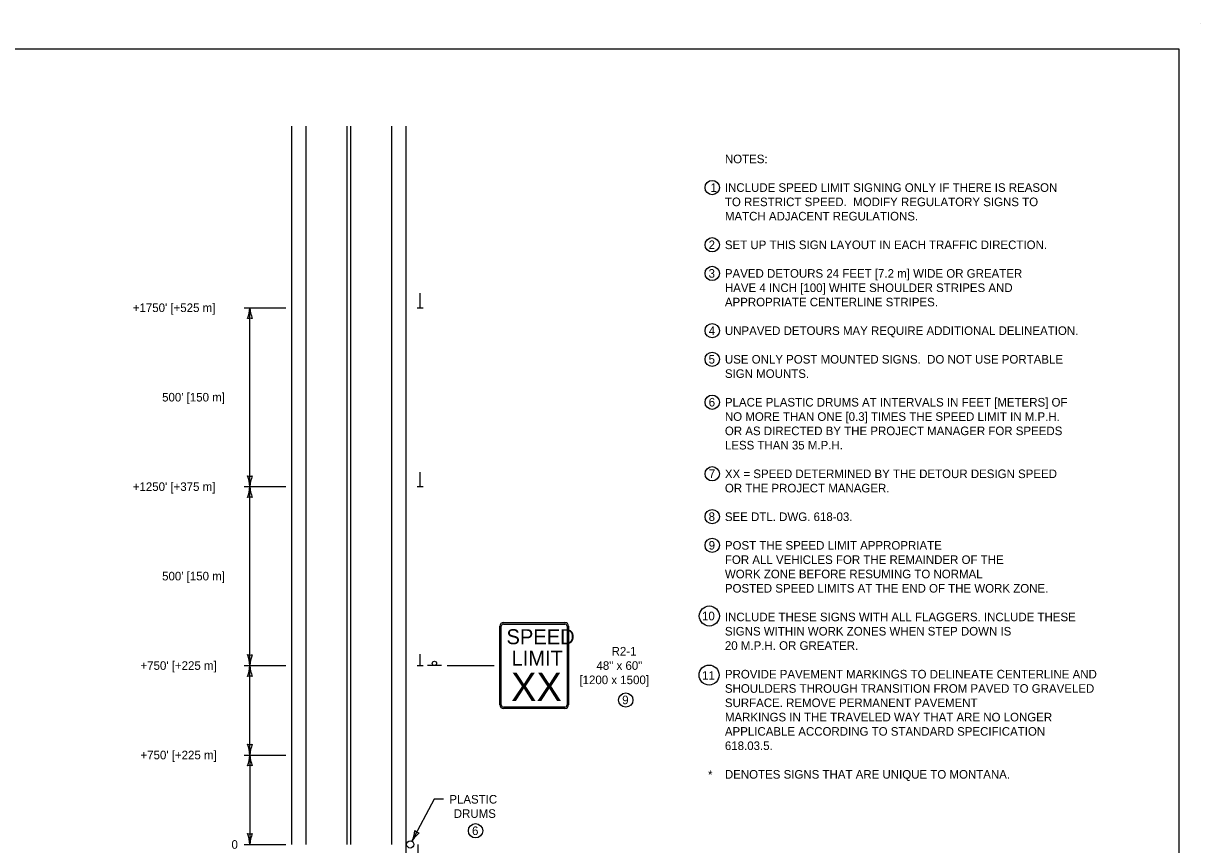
# Model space of a CAD drawing. Extents: x 49991.4 to 50021, y 49987.6 to 50011.4.
# Drawn here: x 50008.68 to 50016.9, y 49993.44 to 49999.18 of the extents above; entities that cross this region are included whole.
import ezdxf

# ---------------------------------------------------------------- set-up
doc = ezdxf.new("R2010")
doc.units = 0
for name, color, linetype in [('Level 1', 7, 'Continuous'), ('Level 2', 7, 'Continuous'), ('Level 3', 7, 'Continuous')]:
    doc.layers.add(name, color=color, linetype=linetype)

msp = doc.modelspace()

# ---------------------------------------------------------------- linework, layer by layer
at = {"layer": 'Level 1'}
for p, q in [((50016.9001, 49999.1756), (50016.9001, 49999.1756)), ((50010.5474, 49998.459), (50010.5474, 49993.4398)), ((50010.6474, 49998.459), (50010.6474, 49993.4398)), ((50010.9349, 49998.459), (50010.9349, 49993.4398)), ((50010.9599, 49998.459), (50010.9599, 49993.4398)), ((50011.2474, 49998.459), (50011.2474, 49993.4398)), ((50011.3474, 49998.459), (50011.3474, 49989.3327)), ((50011.4474, 49997.1898), (50011.4474, 49997.2918)), ((50011.4271, 49997.1898), (50011.4677, 49997.1898)), ((50011.4474, 49995.9398), (50011.4474, 49996.0417)), ((50011.4271, 49995.9398), (50011.4677, 49995.9398)), ((50012.0041, 49994.4148), (50012.0041, 49994.9648)), ((50012.0141, 49994.4148), (50012.0141, 49994.9648)), ((50012.0291, 49994.9898), (50012.4591, 49994.9898)), ((50012.0291, 49994.9798), (50012.4591, 49994.9798)), ((50012.4741, 49994.9648), (50012.4741, 49994.4148)), ((50012.4841, 49994.9648), (50012.4841, 49994.4148)), ((50011.4474, 49994.6898), (50011.4474, 49994.7682)), ((50011.4271, 49994.6898), (50011.4677, 49994.6898)), ((50011.5954, 49994.6898), (50011.4994, 49994.6898)), ((50012.4591, 49994.3998), (50012.0291, 49994.3998)), ((50012.4591, 49994.3898), (50012.0291, 49994.3898)), ((50011.4344, 49993.3584), (50011.4343, 49993.4398))]:
    msp.add_line(p, q, dxfattribs=at)
msp.add_lwpolyline([(49999.3835, 49998.9992), (50016.7501, 49998.9992), (50016.7501, 49987.7988), (49999.3835, 49987.7988)], close=True, dxfattribs=at)
for centre, radius in [((50011.5473, 49994.705), 0.0152), ((50011.3779, 49993.4398), 0.025)]:
    msp.add_circle(centre, radius, dxfattribs=at)
for centre, radius, start, end in [((50012.029, 49994.9648), 0.025, 90, 180), ((50012.029, 49994.9648), 0.015, 90, 180), ((50012.459, 49994.9648), 0.025, 0, 90), ((50012.459, 49994.9648), 0.015, 0, 90), ((50012.029, 49994.4148), 0.025, 180, 270), ((50012.029, 49994.4148), 0.015, 180, 270), ((50012.459, 49994.4148), 0.025, 270, 0), ((50012.459, 49994.4148), 0.015, 270, 0)]:
    msp.add_arc(centre, radius, start, end, dxfattribs=at)
at = {"layer": 'Level 2'}
for centre, radius in [((50013.488, 49998.0295), 0.05), ((50013.488, 49997.6295), 0.05), ((50013.488, 49997.4295), 0.05), ((50013.488, 49997.0295), 0.05), ((50013.488, 49996.8295), 0.05), ((50013.488, 49996.5295), 0.05), ((50013.488, 49996.0295), 0.05), ((50013.488, 49995.7297), 0.05), ((50013.488, 49995.5298), 0.05), ((50013.468, 49995.036), 0.07), ((50013.466, 49994.6235), 0.07), ((50012.8839, 49994.4487), 0.05), ((50011.8342, 49993.5356), 0.05)]:
    msp.add_circle(centre, radius, dxfattribs=at)
at = {"layer": 'Level 3'}
for p, q in [((50010.2174, 49997.1898), (50010.5074, 49997.1898)), ((50010.2574, 49995.9398), (50010.2574, 49997.1898)), ((50010.2174, 49995.9398), (50010.5074, 49995.9398)), ((50010.2574, 49994.6898), (50010.2574, 49995.9398)), ((50010.2174, 49994.6898), (50010.5074, 49994.6898)), ((50010.2574, 49994.0648), (50010.2574, 49994.6898)), ((50011.6354, 49994.6898), (50011.9641, 49994.6898)), ((50010.2174, 49994.0648), (50010.5074, 49994.0648)), ((50010.2574, 49994.0648), (50010.2574, 49993.4398)), ((50011.5443, 49993.7556), (50011.3897, 49993.4618)), ((50011.6106, 49993.7556), (50011.5443, 49993.7556)), ((50010.2174, 49993.4398), (50010.5074, 49993.4398))]:
    msp.add_line(p, q, dxfattribs=at)
for centre, radius, start, end in [((50010.0247, 49997.2013), 0.233, 337.92284, 357.17269), ((50010.4795, 49997.199), 0.2223, 182.36048, 202.54399), ((50010.2574, 49997.0616), 0.0548, 72.13882, 107.86118), ((50010.0353, 49995.9306), 0.2223, 2.36048, 22.54399), ((50010.2574, 49996.068), 0.0548, 252.13882, 287.86118), ((50010.4901, 49995.9283), 0.233, 157.92284, 177.17269), ((50010.0353, 49995.949), 0.2223, 337.45491, 357.63841), ((50010.2574, 49995.8116), 0.0548, 72.13771, 107.86008), ((50010.4901, 49995.9513), 0.233, 182.82621, 202.07606), ((50010.2574, 49994.818), 0.0548, 252.13771, 287.86008), ((50010.0247, 49994.6783), 0.233, 2.82621, 22.07606), ((50010.4795, 49994.6806), 0.2223, 157.45491, 177.63841), ((50010.0247, 49994.7013), 0.233, 337.92284, 357.17269), ((50010.4795, 49994.699), 0.2223, 182.36048, 202.54399), ((50010.2574, 49994.5616), 0.0548, 72.13882, 107.86118), ((50010.0352, 49994.0556), 0.2223, 2.36048, 22.54399), ((50010.2574, 49994.193), 0.0548, 252.13882, 287.86118), ((50010.4901, 49994.0533), 0.233, 157.92284, 177.17269), ((50010.0247, 49994.0763), 0.233, 337.92284, 357.17269), ((50010.4795, 49994.074), 0.2223, 182.36048, 202.54399), ((50010.2574, 49993.9366), 0.0548, 72.13882, 107.86118), ((50010.0352, 49993.4306), 0.2223, 2.36048, 22.54399), ((50010.2574, 49993.568), 0.0548, 252.13882, 287.86118), ((50010.4901, 49993.4283), 0.233, 157.92284, 177.17269), ((50011.1788, 49993.5609), 0.233, 334.82731, 354.07716), ((50011.5815, 49993.3494), 0.2223, 129.45601, 149.63952), ((50011.4499, 49993.575), 0.0548, 224.13882, 259.86118)]:
    msp.add_arc(centre, radius, start, end, dxfattribs=at)

# ---------------------------------------------------------------- texts
at = {"layer": 'Level 1'}
for s, height, p in [('SPEED', 0.10512, (50012.0503, 49994.8388)), ('LIMIT', 0.10512, (50012.0857, 49994.6887)), ('XX', 0.1989, (50012.0825, 49994.4414))]:
    msp.add_text(s, height=height, dxfattribs=at).set_placement(p)
at = {"layer": 'Level 2'}
for s, p in [('NOTES:', (50013.5768, 49998.1996)), ('1', (50013.4768, 49997.9997)), ('INCLUDE SPEED LIMIT SIGNING ONLY IF THERE IS REASON', (50013.5768, 49997.9996)), ('TO RESTRICT SPEED.  MODIFY REGULATORY SIGNS TO', (50013.5768, 49997.8996)), ('MATCH ADJACENT REGULATIONS.', (50013.5768, 49997.7996)), ('2', (50013.4629, 49997.5997)), ('SET UP THIS SIGN LAYOUT IN EACH TRAFFIC DIRECTION.', (50013.5768, 49997.5996)), ('3', (50013.4628, 49997.3997)), ('PAVED DETOURS 24 FEET [7.2 m] WIDE OR GREATER', (50013.5768, 49997.3996)), ('HAVE 4 INCH [100] WHITE SHOULDER STRIPES AND ', (50013.5768, 49997.2996)), ('APPROPRIATE CENTERLINE STRIPES.', (50013.5768, 49997.1996)), ("+1750' [+525 m]", (50009.4389, 49997.1598)), ('4', (50013.4641, 49996.9997)), ('UNPAVED DETOURS MAY REQUIRE ADDITIONAL DELINEATION.', (50013.5768, 49996.9996)), ('5', (50013.4631, 49996.7997)), ('USE ONLY POST MOUNTED SIGNS.  DO NOT USE PORTABLE', (50013.5768, 49996.7996)), ('SIGN MOUNTS.', (50013.5768, 49996.6996)), ("500' [150 m]", (50009.644, 49996.5348)), ('6', (50013.4636, 49996.4997)), ('PLACE PLASTIC DRUMS AT INTERVALS IN FEET [METERS] OF', (50013.5768, 49996.4996)), ('NO MORE THAN ONE [0.3] TIMES THE SPEED LIMIT IN M.P.H. ', (50013.5768, 49996.3996)), ('OR AS DIRECTED BY THE PROJECT MANAGER FOR SPEEDS ', (50013.5768, 49996.2996)), ('LESS THAN 35 M.P.H.', (50013.5768, 49996.1996)), ('7', (50013.4642, 49995.9997)), ('XX = SPEED DETERMINED BY THE DETOUR DESIGN SPEED', (50013.5768, 49995.9996)), ("+1250' [+375 m]", (50009.4389, 49995.9098)), ('OR THE PROJECT MANAGER.', (50013.5768, 49995.8996)), ('8', (50013.4631, 49995.6999)), ('SEE DTL. DWG. 618-03.', (50013.5768, 49995.6996)), ('9', (50013.4635, 49995.5)), ('POST THE SPEED LIMIT APPROPRIATE', (50013.5768, 49995.4996)), ('FOR ALL VEHICLES FOR THE REMAINDER OF THE', (50013.5768, 49995.3996)), ("500' [150 m]", (50009.644, 49995.2848)), ('WORK ZONE BEFORE RESUMING TO NORMAL', (50013.5768, 49995.2996)), ('POSTED SPEED LIMITS AT THE END OF THE WORK ZONE.', (50013.5768, 49995.1996)), ('10', (50013.4168, 49995.006)), ('INCLUDE THESE SIGNS WITH ALL FLAGGERS. INCLUDE THESE', (50013.5768, 49994.9996)), ('SIGNS WITHIN WORK ZONES WHEN STEP DOWN IS', (50013.5768, 49994.8996)), ('R2-1', (50012.7851, 49994.7598)), ('20 M.P.H. OR GREATER.', (50013.5768, 49994.7996)), ("+750' [+225 m]", (50009.4928, 49994.6598)), ('48" x 60"', (50012.6795, 49994.6598)), ('11', (50013.4171, 49994.5905)), ('PROVIDE PAVEMENT MARKINGS TO DELINEATE CENTERLINE AND', (50013.5768, 49994.5996)), ('[1200 x 1500]', (50012.5601, 49994.5598)), ('SHOULDERS THROUGH TRANSITION FROM PAVED TO GRAVELED', (50013.5768, 49994.4996)), ('9', (50012.859, 49994.4198)), ('SURFACE. REMOVE PERMANENT PAVEMENT ', (50013.5768, 49994.3996)), ('MARKINGS IN THE TRAVELED WAY THAT ARE NO LONGER', (50013.5768, 49994.2996)), ('APPLICABLE ACCORDING TO STANDARD SPECIFICATION ', (50013.5768, 49994.1996)), ('618.03.5.', (50013.5768, 49994.0996)), ("+750' [+225 m]", (50009.4928, 49994.0348)), ('*', (50013.4586, 49993.8977)), ('DENOTES SIGNS THAT ARE UNIQUE TO MONTANA.', (50013.5768, 49993.8996)), ('PLASTIC', (50011.6509, 49993.7256)), ('DRUMS', (50011.6822, 49993.6256)), ('6', (50011.8098, 49993.5057)), ('0', (50010.1288, 49993.4098))]:
    msp.add_text(s, height=0.06, dxfattribs=at).set_placement(p)

doc.saveas('drawing.dxf')
